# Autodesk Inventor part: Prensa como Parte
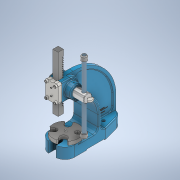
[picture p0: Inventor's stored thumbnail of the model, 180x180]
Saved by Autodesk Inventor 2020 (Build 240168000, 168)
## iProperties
Created: 2019-09
Part Number: Prensa como Parte
Material: Generic
Document SubType Name: Modeling
Designer: user
Density: 1 g/cm^3
Appearance: Default
Author: user
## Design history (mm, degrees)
derived "Arbor_Press.iam"
body "Solid1"
node "Arbor_Frame.ipt:1"
node "FACE PLATE.ipt:1"
body "Solid2"
node "PINION SHAFT.ipt:1"
body "Solid3"
node "LEVER ARM.ipt:1"
body "Solid4"
node "THUMB SCREW.ipt:1"
body "Solid5"
node "TABLE PLATE.ipt:1"
body "Solid6"
node "RAM.ipt:1"
body "Solid7"
node "HANDLE CAP.ipt:1"
body "Solid8"
node "HANDLE CAP.ipt:2"
body "Solid9"
node "COLLAR.ipt:1"
body "Solid10"
node "GIB PLATE.ipt:1"
body "Solid11"
node "GROOVE PIN.ipt:1"
body "Solid12"
node "Hexagon Socket Head Cap Screw - Inch 1/4 - 20 UNC - 7/8:9"
body "Solid13"
node "Hexagon Socket Head Cap Screw - Inch 1/4 - 20 UNC - 7/8:10"
body "Solid14"
node "Hexagon Socket Head Cap Screw - Inch 1/4 - 20 UNC - 7/8:11"
body "Solid15"
node "Hexagon Socket Head Cap Screw - Inch 1/4 - 20 UNC - 7/8:12"
body "Solid16"
node "ISO 4766 M5 x 5:1"
body "Solid17"
node "ISO 4026 M5 x 16:1"
body "Solid18"
node "ISO 4026 M5 x 16:2"
body "Solid19"
node "ISO 4026 M5 x 16:3"
body "Solid20"
node "ISO 4026 M5 x 16:4"
body "Solid21"
